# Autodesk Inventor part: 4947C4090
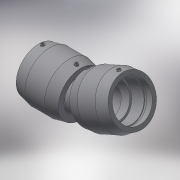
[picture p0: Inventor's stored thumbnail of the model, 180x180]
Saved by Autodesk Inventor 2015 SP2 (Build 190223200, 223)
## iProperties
Created: 2017-06
Part Number: 4947C4090
Material: Generic
Description: PLASSON ADJUSTABLE ELBOW 90
Document SubType Name: Modeling
Designer: KIM
Mass: 1365.57 g
Surface Area: 2282.49 cm^2
Volume: 1365.57 cm^3
Density: 1 g/cm^3
Appearance: Default
Author: KIM
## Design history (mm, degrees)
derived "4947C4.ipt"
feature "Solid1::4947C4.ipt"
tag "TaggingFeature1"
body "Solid1"
other parameters: "d0" = 136.4, "d2" = 116, "d3" = 72, "d4" = 36, "d5" = 104.4, "d8" = 168 deg, "d10" = 28.8, "d11" = 9.6, "d29" = 77, "d30" = 15, "d31" = 54.56, "d34" = 5 deg, "d41" = 4, "d42" = 14, "d43" = 0, "d48" = 81, "d49" = 24 deg, "d50" = 341, "d51" = 78 deg, "d52" = 90 deg, "d55" = 32.2, "d57" = 168 deg, "d58" = 6.44, "d60" = 39.68667, "d62" = 3, "d63" = 0, "L_" = 341, "L_1" = 72, "D_" = 116, "A_" = 77, "d_2" = 12, "L_0" = 148, "d54" = 64.4, "d59" = 132.28891
